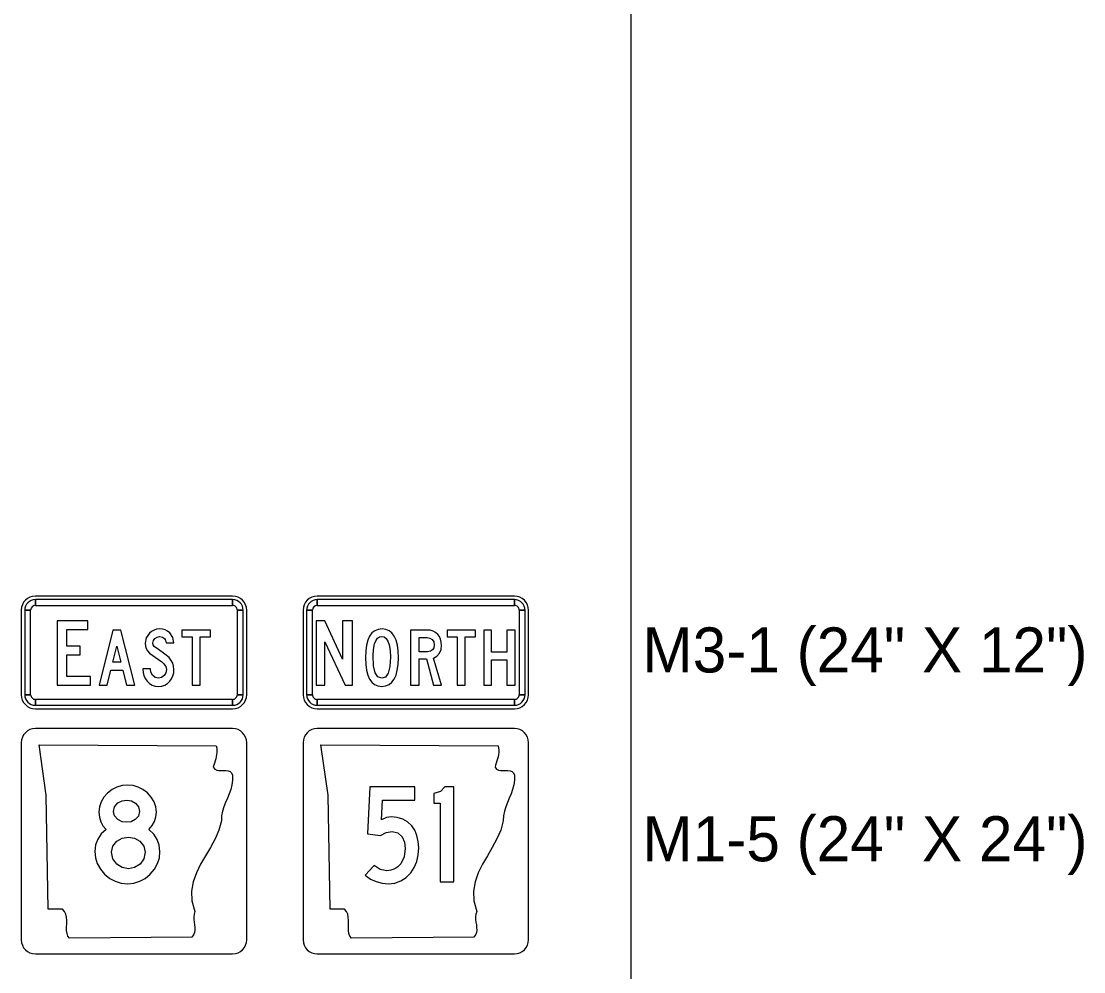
# Model space of a CAD drawing. Extents: x 1001568 to 1002149, y 1840825 to 1841423.
# Drawn here: x 1001915.24 to 1001924.67, y 1841286.31 to 1841294.75 of the extents above; entities that cross this region are included whole.
import ezdxf

# ---------------------------------------------------------------- set-up
doc = ezdxf.new("R2010")
doc.units = 0
for name, color, linetype in [('40', 7, 'Continuous'), ('R_No Plot', 7, 'Continuous'), ('SIGNS', 7, 'Continuous')]:
    doc.layers.add(name, color=color, linetype=linetype)

msp = doc.modelspace()

# ---------------------------------------------------------------- linework, layer by layer
at = {"layer": 'R_No Plot'}
msp.add_line((1001920.6501, 1841310.6666), (1001920.6501, 1841248.1274), dxfattribs=at)
at = {"layer": 'SIGNS'}
for p, q in [((1001917.1176, 1841289.6447), (1001915.3676, 1841289.6447)), ((1001919.6176, 1841289.6447), (1001917.8676, 1841289.6447)), ((1001915.3676, 1841289.5614), (1001915.3676, 1841289.6135)), ((1001917.1176, 1841289.6135), (1001917.1176, 1841289.5614)), ((1001917.8676, 1841289.5614), (1001917.8676, 1841289.6135)), ((1001919.6176, 1841289.6135), (1001919.6176, 1841289.5614)), ((1001915.2426, 1841289.5197), (1001915.2426, 1841288.7697)), ((1001915.2738, 1841289.5197), (1001915.3259, 1841289.5197)), ((1001917.1592, 1841289.5197), (1001917.2113, 1841289.5197)), ((1001917.2426, 1841288.7697), (1001917.2426, 1841289.5197)), ((1001917.7426, 1841289.5197), (1001917.7426, 1841288.7697)), ((1001917.7738, 1841289.5197), (1001917.8259, 1841289.5197)), ((1001919.6592, 1841289.5197), (1001919.7113, 1841289.5197)), ((1001919.7426, 1841288.7697), (1001919.7426, 1841289.5197)), ((1001915.3259, 1841288.7697), (1001915.2738, 1841288.7697)), ((1001915.3676, 1841288.676), (1001915.3676, 1841288.7281)), ((1001917.1176, 1841288.7281), (1001917.1176, 1841288.676)), ((1001917.2113, 1841288.7697), (1001917.1592, 1841288.7697)), ((1001917.8259, 1841288.7697), (1001917.7738, 1841288.7697)), ((1001917.8676, 1841288.676), (1001917.8676, 1841288.7281)), ((1001919.6176, 1841288.7281), (1001919.6176, 1841288.676)), ((1001919.7113, 1841288.7697), (1001919.6592, 1841288.7697)), ((1001915.3676, 1841288.6447), (1001917.1176, 1841288.6447)), ((1001917.8676, 1841288.6447), (1001919.6176, 1841288.6447)), ((1001917.1176, 1841288.4691), (1001915.3676, 1841288.4691)), ((1001919.6176, 1841288.4691), (1001917.8676, 1841288.4691)), ((1001915.2426, 1841288.3441), (1001915.2426, 1841286.5941)), ((1001917.2426, 1841286.5941), (1001917.2426, 1841288.3441)), ((1001917.7426, 1841288.3441), (1001917.7426, 1841286.5941)), ((1001919.7426, 1841286.5941), (1001919.7426, 1841288.3441)), ((1001915.2426, 1841286.5941), (1001915.2426, 1841286.5941)), ((1001917.7426, 1841286.5941), (1001917.7426, 1841286.5941)), ((1001915.3676, 1841286.4691), (1001917.1176, 1841286.4691)), ((1001917.8676, 1841286.4691), (1001919.6176, 1841286.4691))]:
    msp.add_line(p, q, dxfattribs=at)
for points in [[(1001917.1176, 1841289.6135), (1001915.3676, 1841289.6135), (1001915.3676, 1841289.5614), (1001917.1176, 1841289.5614), (1001917.1176, 1841289.6135), (1001917.1176, 1841289.6135)], [(1001919.6176, 1841289.6135), (1001917.8676, 1841289.6135), (1001917.8676, 1841289.5614), (1001919.6176, 1841289.5614), (1001919.6176, 1841289.6135), (1001919.6176, 1841289.6135)], [(1001915.2738, 1841289.5197), (1001915.2738, 1841288.7697), (1001915.3259, 1841288.7697), (1001915.3259, 1841289.5197), (1001915.2738, 1841289.5197), (1001915.2738, 1841289.5197)], [(1001917.2113, 1841288.7697), (1001917.2113, 1841289.5197), (1001917.1592, 1841289.5197), (1001917.1592, 1841288.7697), (1001917.2113, 1841288.7697), (1001917.2113, 1841288.7697)], [(1001917.7738, 1841289.5197), (1001917.7738, 1841288.7697), (1001917.8259, 1841288.7697), (1001917.8259, 1841289.5197), (1001917.7738, 1841289.5197), (1001917.7738, 1841289.5197)], [(1001919.7113, 1841288.7697), (1001919.7113, 1841289.5197), (1001919.6592, 1841289.5197), (1001919.6592, 1841288.7697), (1001919.7113, 1841288.7697), (1001919.7113, 1841288.7697)], [(1001915.8561, 1841288.9315), (1001915.6455, 1841288.9315), (1001915.6455, 1841289.1222), (1001915.765, 1841289.1222), (1001915.765, 1841289.2008), (1001915.6455, 1841289.2008), (1001915.6455, 1841289.3466), (1001915.8343, 1841289.3466), (1001915.8343, 1841289.4252), (1001915.5619, 1841289.4252), (1001915.5619, 1841288.8531), (1001915.8561, 1841288.8531)], [(1001916.3205, 1841289.0004), (1001916.3205, 1841288.9959), (1001916.3226, 1841288.966), (1001916.3296, 1841288.9384), (1001916.3417, 1841288.913), (1001916.3585, 1841288.8899), (1001916.3796, 1841288.8694), (1001916.4037, 1841288.855), (1001916.4301, 1841288.8464), (1001916.4594, 1841288.8435), (1001916.4886, 1841288.8462), (1001916.5152, 1841288.8547), (1001916.5388, 1841288.8687), (1001916.5598, 1841288.8885), (1001916.5762, 1841288.9112), (1001916.5879, 1841288.9363), (1001916.595, 1841288.9635), (1001916.5973, 1841288.9932), (1001916.5945, 1841289.0216), (1001916.5862, 1841289.0486), (1001916.5724, 1841289.0742), (1001916.5533, 1841289.0984), (1001916.5164, 1841289.1302), (1001916.4594, 1841289.1693), (1001916.4218, 1841289.1976), (1001916.4136, 1841289.2118), (1001916.4109, 1841289.2282), (1001916.4153, 1841289.2501), (1001916.4285, 1841289.2686), (1001916.4476, 1841289.281), (1001916.4703, 1841289.2853), (1001916.4946, 1841289.2812), (1001916.5123, 1841289.2695), (1001916.5219, 1841289.2529), (1001916.5292, 1841289.2283), (1001916.5973, 1841289.2283), (1001916.5862, 1841289.2784), (1001916.5602, 1841289.3177), (1001916.5412, 1841289.3331), (1001916.5197, 1841289.3442), (1001916.4952, 1841289.3508), (1001916.4683, 1841289.3531), (1001916.4434, 1841289.3506), (1001916.4203, 1841289.3435), (1001916.399, 1841289.3317), (1001916.3798, 1841289.3152), (1001916.3519, 1841289.274), (1001916.3427, 1841289.2262), (1001916.345, 1841289.2016), (1001916.352, 1841289.1791), (1001916.3637, 1841289.1582), (1001916.3802, 1841289.1393), (1001916.4599, 1841289.0823), (1001916.4895, 1841289.0598), (1001916.5078, 1841289.0431), (1001916.524, 1841289.0186), (1001916.5296, 1841288.9925), (1001916.5248, 1841288.9635), (1001916.5108, 1841288.9388), (1001916.4877, 1841288.9208), (1001916.4594, 1841288.9148), (1001916.4293, 1841288.9214), (1001916.4059, 1841288.9415), (1001916.3923, 1841288.9683), (1001916.3882, 1841289.0004)], [(1001917.8579, 1841288.8531), (1001917.9364, 1841288.8531), (1001917.9364, 1841289.2395), (1001918.117, 1841288.8531), (1001918.1809, 1841288.8531), (1001918.1809, 1841289.4252), (1001918.0935, 1841289.4252), (1001918.0935, 1841289.0839), (1001917.9364, 1841289.4252), (1001917.8579, 1841289.4252)], [(1001916.7578, 1841288.8531), (1001916.8289, 1841288.8531), (1001916.8289, 1841289.2818), (1001916.9204, 1841289.2818), (1001916.9204, 1841289.3434), (1001916.6682, 1841289.3434), (1001916.6682, 1841289.2818), (1001916.7578, 1841289.2818)], [(1001919.1098, 1841288.8531), (1001919.1809, 1841288.8531), (1001919.1809, 1841289.2818), (1001919.2724, 1841289.2818), (1001919.2724, 1841289.3434), (1001919.0202, 1841289.3434), (1001919.0202, 1841289.2818), (1001919.1098, 1841289.2818)], [(1001919.3472, 1841288.8531), (1001919.4145, 1841288.8531), (1001919.4145, 1841289.0781), (1001919.5491, 1841289.0781), (1001919.5491, 1841288.8531), (1001919.6241, 1841288.8531), (1001919.6241, 1841289.3434), (1001919.5491, 1841289.3434), (1001919.5491, 1841289.1468), (1001919.4145, 1841289.1468), (1001919.4145, 1841289.3434), (1001919.3472, 1841289.3434)], [(1001915.3676, 1841288.676), (1001917.1176, 1841288.676), (1001917.1176, 1841288.7281), (1001915.3676, 1841288.7281), (1001915.3676, 1841288.676), (1001915.3676, 1841288.676)], [(1001917.8676, 1841288.676), (1001919.6176, 1841288.676), (1001919.6176, 1841288.7281), (1001917.8676, 1841288.7281), (1001917.8676, 1841288.676), (1001917.8676, 1841288.676)], [(1001916.9725, 1841288.3147), (1001916.9772, 1841288.2956), (1001916.9788, 1841288.2762), (1001916.9782, 1841288.2571), (1001916.9758, 1841288.238), (1001916.9718, 1841288.2189), (1001916.9671, 1841288.2002), (1001916.9614, 1841288.1811), (1001916.9558, 1841288.1627), (1001916.9504, 1841288.1444), (1001916.9454, 1841288.126), (1001916.9594, 1841288.1099), (1001916.9768, 1841288.1007), (1001916.9965, 1841288.0967), (1001917.0179, 1841288.0963), (1001917.0393, 1841288.097), (1001917.06, 1841288.0974), (1001917.0791, 1841288.0952), (1001917.0958, 1841288.0889), (1001917.1088, 1841288.0768), (1001917.1168, 1841288.0566), (1001917.1175, 1841288.0111), (1001917.1118, 1841287.9685), (1001917.1012, 1841287.9281), (1001917.0868, 1841287.8896), (1001917.0711, 1841287.8514), (1001917.055, 1841287.8136), (1001917.04, 1841287.7751), (1001917.028, 1841287.7354), (1001917.0196, 1841287.6939), (1001917.0176, 1841287.6499), (1001916.9955, 1841287.5676), (1001916.9618, 1841287.4894), (1001916.921, 1841287.4138), (1001916.8769, 1841287.3389), (1001916.8338, 1841287.2644), (1001916.796, 1841287.1884), (1001916.768, 1841287.1098), (1001916.7536, 1841287.0272), (1001916.7569, 1841286.9399), (1001916.7827, 1841286.8463), (1001916.775, 1841286.8231), (1001916.7723, 1841286.7993), (1001916.773, 1841286.7754), (1001916.776, 1841286.7512), (1001916.7793, 1841286.7273), (1001916.782, 1841286.7038), (1001916.7827, 1841286.6807), (1001916.7793, 1841286.659), (1001916.771, 1841286.6377), (1001916.7556, 1841286.6179), (1001915.6719, 1841286.608), (1001915.6572, 1841286.6278), (1001915.6488, 1841286.6517), (1001915.6452, 1841286.6781), (1001915.6448, 1841286.7064), (1001915.6455, 1841286.7361), (1001915.6458, 1841286.7655), (1001915.6438, 1841286.7945), (1001915.6381, 1841286.8213), (1001915.6271, 1841286.8455), (1001915.6087, 1841286.8661), (1001915.4824, 1841286.8661), (1001915.4644, 1841287.8778), (1001915.4009, 1841288.3246), (1001916.9725, 1841288.3147), (1001916.9725, 1841288.3147)], [(1001919.4725, 1841288.3147), (1001919.4772, 1841288.2956), (1001919.4788, 1841288.2762), (1001919.4782, 1841288.2571), (1001919.4758, 1841288.238), (1001919.4718, 1841288.2189), (1001919.4671, 1841288.2002), (1001919.4614, 1841288.1811), (1001919.4558, 1841288.1627), (1001919.4504, 1841288.1444), (1001919.4454, 1841288.126), (1001919.4594, 1841288.1099), (1001919.4768, 1841288.1007), (1001919.4965, 1841288.0967), (1001919.5179, 1841288.0963), (1001919.5393, 1841288.097), (1001919.56, 1841288.0974), (1001919.5791, 1841288.0952), (1001919.5958, 1841288.0889), (1001919.6088, 1841288.0768), (1001919.6168, 1841288.0566), (1001919.6175, 1841288.0111), (1001919.6118, 1841287.9685), (1001919.6012, 1841287.9281), (1001919.5868, 1841287.8896), (1001919.5711, 1841287.8514), (1001919.555, 1841287.8136), (1001919.54, 1841287.7751), (1001919.528, 1841287.7354), (1001919.5196, 1841287.6939), (1001919.5176, 1841287.6499), (1001919.4955, 1841287.5676), (1001919.4618, 1841287.4894), (1001919.421, 1841287.4138), (1001919.3769, 1841287.3389), (1001919.3338, 1841287.2644), (1001919.296, 1841287.1884), (1001919.268, 1841287.1098), (1001919.2536, 1841287.0272), (1001919.2569, 1841286.9399), (1001919.2827, 1841286.8463), (1001919.275, 1841286.8231), (1001919.2723, 1841286.7993), (1001919.273, 1841286.7754), (1001919.276, 1841286.7512), (1001919.2793, 1841286.7273), (1001919.282, 1841286.7038), (1001919.2827, 1841286.6807), (1001919.2793, 1841286.659), (1001919.271, 1841286.6377), (1001919.2556, 1841286.6179), (1001918.1719, 1841286.608), (1001918.1572, 1841286.6278), (1001918.1488, 1841286.6517), (1001918.1452, 1841286.6781), (1001918.1448, 1841286.7064), (1001918.1455, 1841286.7361), (1001918.1458, 1841286.7655), (1001918.1438, 1841286.7945), (1001918.1381, 1841286.8213), (1001918.1271, 1841286.8455), (1001918.1087, 1841286.8661), (1001917.9824, 1841286.8661), (1001917.9644, 1841287.8778), (1001917.9009, 1841288.3246), (1001919.4725, 1841288.3147), (1001919.4725, 1841288.3147)], [(1001918.2929, 1841287.1669), (1001918.3405, 1841287.1339), (1001918.3905, 1841287.1106), (1001918.4427, 1841287.0968), (1001918.4974, 1841287.0922), (1001918.5567, 1841287.0982), (1001918.6098, 1841287.1163), (1001918.6567, 1841287.1468), (1001918.6977, 1841287.1898), (1001918.7284, 1841287.2373), (1001918.7503, 1841287.2899), (1001918.7635, 1841287.3474), (1001918.7681, 1841287.4104), (1001918.7642, 1841287.4678), (1001918.7526, 1841287.52), (1001918.7333, 1841287.5661), (1001918.7062, 1841287.6067), (1001918.6696, 1841287.6412), (1001918.6273, 1841287.6662), (1001918.5783, 1841287.6811), (1001918.5237, 1841287.6863), (1001918.4824, 1841287.6796), (1001918.4388, 1841287.6595), (1001918.448, 1841287.8349), (1001918.7351, 1841287.8349), (1001918.7351, 1841287.9504), (1001918.3343, 1841287.9504), (1001918.3139, 1841287.5345), (1001918.4303, 1841287.5195), (1001918.4793, 1841287.5455), (1001918.5322, 1841287.5543), (1001918.5842, 1841287.5424), (1001918.6222, 1841287.5076), (1001918.6418, 1841287.4616), (1001918.6485, 1841287.4046), (1001918.6384, 1841287.3299), (1001918.6084, 1841287.2687), (1001918.584, 1841287.2417), (1001918.5553, 1841287.2228), (1001918.5221, 1841287.2112), (1001918.4847, 1841287.2077), (1001918.4274, 1841287.2193), (1001918.3735, 1841287.2546)], [(1001918.9574, 1841287.1086), (1001919.0804, 1841287.1086), (1001919.0804, 1841287.9504), (1001918.999, 1841287.9504), (1001918.9607, 1841287.9091), (1001918.9023, 1841287.8936), (1001918.9023, 1841287.8055), (1001918.9574, 1841287.8055)]]:
    msp.add_lwpolyline(points, close=True, dxfattribs=at)
for points in [[(1001918.5878, 1841289.099), (1001918.5854, 1841289.1583), (1001918.5787, 1841289.21), (1001918.5674, 1841289.2536), (1001918.5516, 1841289.2895), (1001918.531, 1841289.3171), (1001918.5062, 1841289.3371), (1001918.4768, 1841289.349), (1001918.443, 1841289.3531), (1001918.4084, 1841289.349), (1001918.3785, 1841289.3371), (1001918.3533, 1841289.3171), (1001918.3327, 1841289.2895), (1001918.3166, 1841289.2536), (1001918.3052, 1841289.21), (1001918.2983, 1841289.1583), (1001918.2961, 1841289.099), (1001918.2982, 1841289.0389), (1001918.3049, 1841288.987), (1001918.3162, 1841288.943), (1001918.332, 1841288.9073), (1001918.3521, 1841288.8792), (1001918.3769, 1841288.8594), (1001918.4062, 1841288.8474), (1001918.44, 1841288.8435), (1001918.4745, 1841288.8474), (1001918.5046, 1841288.8594), (1001918.53, 1841288.8792), (1001918.5508, 1841288.9073), (1001918.567, 1841288.943), (1001918.5785, 1841288.987), (1001918.5854, 1841289.0389), (1001918.5878, 1841289.099)], [(1001915.9327, 1841288.8531), (1001916.0039, 1841288.8531), (1001916.0371, 1841288.9881), (1001916.1429, 1841288.9881), (1001916.1776, 1841288.8531), (1001916.2493, 1841288.8531), (1001916.1256, 1841289.3434), (1001916.0563, 1841289.3434), (1001915.9327, 1841288.8531)], [(1001918.5172, 1841289.1012), (1001918.5124, 1841289.0195), (1001918.498, 1841288.9613), (1001918.4741, 1841288.9264), (1001918.4407, 1841288.9148), (1001918.4068, 1841288.9271), (1001918.3826, 1841288.9644), (1001918.3682, 1841289.0264), (1001918.3633, 1841289.1136), (1001918.3664, 1841289.1714), (1001918.3757, 1841289.2195), (1001918.3868, 1841289.2489), (1001918.4014, 1841289.2702), (1001918.4192, 1841289.2829), (1001918.4407, 1841289.2872), (1001918.4618, 1841289.2826), (1001918.4797, 1841289.2686), (1001918.4942, 1841289.2453), (1001918.5055, 1841289.213), (1001918.5142, 1841289.1621), (1001918.5172, 1841289.1012)], [(1001918.6939, 1841288.8531), (1001918.7708, 1841288.8531), (1001918.7708, 1841289.0865), (1001918.8363, 1841289.0865), (1001918.9005, 1841288.8531), (1001918.9708, 1841288.8531), (1001918.8995, 1841289.0948), (1001918.9299, 1841289.1119), (1001918.9531, 1841289.139), (1001918.9662, 1841289.1703), (1001918.9708, 1841289.2061), (1001918.9687, 1841289.2356), (1001918.9623, 1841289.262), (1001918.952, 1841289.2851), (1001918.9376, 1841289.3051), (1001918.9185, 1841289.3218), (1001918.8959, 1841289.3338), (1001918.8699, 1841289.341), (1001918.8406, 1841289.3434), (1001918.6939, 1841289.3434), (1001918.6939, 1841288.8531)], [(1001918.7708, 1841289.1511), (1001918.7708, 1841289.2761), (1001918.8428, 1841289.2761), (1001918.868, 1841289.2718), (1001918.8881, 1841289.2591), (1001918.9011, 1841289.2392), (1001918.9054, 1841289.2133), (1001918.9015, 1841289.186), (1001918.8903, 1841289.1666), (1001918.8715, 1841289.1549), (1001918.8452, 1841289.1511), (1001918.7708, 1841289.1511)], [(1001916.0544, 1841289.0578), (1001916.089, 1841289.2002), (1001916.1256, 1841289.0578), (1001916.0544, 1841289.0578)], [(1001915.3676, 1841288.4691), (1001915.3676, 1841288.4691)], [(1001917.1176, 1841288.4691), (1001917.1176, 1841288.4691)], [(1001917.8676, 1841288.4691), (1001917.8676, 1841288.4691)], [(1001919.6176, 1841288.4691), (1001919.6176, 1841288.4691)], [(1001915.2426, 1841288.3441), (1001915.2426, 1841288.3441)], [(1001917.7426, 1841288.3441), (1001917.7426, 1841288.3441)], [(1001916.3755, 1841287.5744), (1001916.4039, 1841287.6077), (1001916.4242, 1841287.6443), (1001916.4366, 1841287.6843), (1001916.4408, 1841287.7276), (1001916.4356, 1841287.7754), (1001916.4209, 1841287.8199), (1001916.3961, 1841287.861), (1001916.3619, 1841287.8984), (1001916.3221, 1841287.9282), (1001916.2798, 1841287.9497), (1001916.2339, 1841287.9626), (1001916.1851, 1841287.967), (1001916.1364, 1841287.9623), (1001916.0907, 1841287.9492), (1001916.048, 1841287.9272), (1001916.0083, 1841287.8966), (1001915.9744, 1841287.8597), (1001915.9504, 1841287.8192), (1001915.9361, 1841287.775), (1001915.9314, 1841287.7276), (1001915.9352, 1841287.6822), (1001915.9474, 1841287.6418), (1001915.9675, 1841287.6056), (1001915.9959, 1841287.5744), (1001915.952, 1841287.5345), (1001915.9208, 1841287.4885), (1001915.902, 1841287.4367), (1001915.8958, 1841287.3789), (1001915.901, 1841287.3227), (1001915.9172, 1841287.2706), (1001915.9442, 1841287.2221), (1001915.9822, 1841287.1775), (1001916.0273, 1841287.1398), (1001916.0761, 1841287.1133), (1001916.1286, 1841287.0974), (1001916.1851, 1841287.0922), (1001916.2412, 1841287.0974), (1001916.2938, 1841287.1133), (1001916.3422, 1841287.1398), (1001916.3871, 1841287.1775), (1001916.4245, 1841287.2221), (1001916.4514, 1841287.2706), (1001916.4676, 1841287.3227), (1001916.4729, 1841287.3789), (1001916.4668, 1841287.4343), (1001916.4485, 1841287.4857), (1001916.418, 1841287.5324), (1001916.3755, 1841287.5744)], [(1001916.2919, 1841287.7315), (1001916.2824, 1841287.6917), (1001916.2537, 1841287.6605), (1001916.2179, 1841287.6427), (1001916.1779, 1841287.6368), (1001916.1364, 1841287.6427), (1001916.0998, 1841287.6614), (1001916.0704, 1841287.6933), (1001916.0609, 1841287.7341), (1001916.0704, 1841287.7754), (1001916.0998, 1841287.8086), (1001916.1364, 1841287.8282), (1001916.1779, 1841287.8349), (1001916.2197, 1841287.828), (1001916.2561, 1841287.8078), (1001916.2829, 1841287.7738), (1001916.2919, 1841287.7315)], [(1001916.3414, 1841287.3706), (1001916.3301, 1841287.3136), (1001916.2963, 1841287.2665), (1001916.2479, 1841287.2347), (1001916.1934, 1841287.2241), (1001916.1392, 1841287.2347), (1001916.0916, 1841287.2667), (1001916.0559, 1841287.3141), (1001916.0443, 1841287.3706), (1001916.0559, 1841287.4253), (1001916.0916, 1841287.4692), (1001916.138, 1841287.4957), (1001916.1934, 1841287.5047), (1001916.2483, 1841287.4957), (1001916.295, 1841287.4692), (1001916.3298, 1841287.4253), (1001916.3414, 1841287.3706)], [(1001915.3676, 1841286.4691), (1001915.3676, 1841286.4691)], [(1001917.1176, 1841286.4691), (1001917.1176, 1841286.4691)], [(1001917.8676, 1841286.4691), (1001917.8676, 1841286.4691)], [(1001919.6176, 1841286.4691), (1001919.6176, 1841286.4691)]]:
    msp.add_lwpolyline(points, dxfattribs=at)
for centre, radius, start, end in [((1001915.3676, 1841289.5197), 0.125, 90.00021, 179.99985), ((1001917.1176, 1841289.5197), 0.125, 0, 90.00021), ((1001917.8676, 1841289.5197), 0.125, 90.00021, 179.99985), ((1001919.6176, 1841289.5197), 0.125, 0, 90.00021), ((1001915.3676, 1841289.5197), 0.0937, 90.00021, 179.99985), ((1001915.3676, 1841289.5197), 0.0417, 90.00021, 179.99985), ((1001917.1176, 1841289.5197), 0.0937, 0, 90.00021), ((1001917.1176, 1841289.5197), 0.0417, 0, 90.00021), ((1001917.8676, 1841289.5197), 0.0937, 90.00021, 179.99985), ((1001917.8676, 1841289.5197), 0.0417, 90.00021, 179.99985), ((1001919.6176, 1841289.5197), 0.0937, 0, 90.00021), ((1001919.6176, 1841289.5197), 0.0417, 0, 90.00021), ((1001915.3676, 1841288.7697), 0.125, 179.99985, 270.00006), ((1001915.3676, 1841288.7697), 0.0937, 179.99985, 270.00006), ((1001915.3676, 1841288.7697), 0.0417, 179.99985, 270.00006), ((1001917.1176, 1841288.7697), 0.125, 270.00006, 0.00027), ((1001917.1176, 1841288.7697), 0.0937, 270.00006, 0.00027), ((1001917.1176, 1841288.7697), 0.0417, 270.00006, 0.00027), ((1001917.8676, 1841288.7697), 0.125, 179.99985, 270.00006), ((1001917.8676, 1841288.7697), 0.0937, 179.99985, 270.00006), ((1001917.8676, 1841288.7697), 0.0417, 179.99985, 270.00006), ((1001919.6176, 1841288.7697), 0.125, 270.00006, 0.00027), ((1001919.6176, 1841288.7697), 0.0937, 270.00006, 0.00027), ((1001919.6176, 1841288.7697), 0.0417, 270.00006, 0.00027), ((1001915.3676, 1841288.3441), 0.125, 90.00021, 179.99985), ((1001917.1176, 1841288.3441), 0.125, 0, 90), ((1001917.8676, 1841288.3441), 0.125, 90.00021, 179.99985), ((1001919.6176, 1841288.3441), 0.125, 0, 90), ((1001915.3676, 1841286.5941), 0.125, 180, 270), ((1001917.1176, 1841286.5941), 0.125, 270.00006, 0.00027), ((1001917.8676, 1841286.5941), 0.125, 180, 270), ((1001919.6176, 1841286.5941), 0.125, 270.00006, 0.00027)]:
    msp.add_arc(centre, radius, start, end, dxfattribs=at)

# ---------------------------------------------------------------- texts
at = {"layer": '40'}
for s, p in [('M3-1 (24" X 12")', (1001920.7531, 1841288.9666)), ('M1-5 (24" X 24")', (1001920.7531, 1841287.2911))]:
    msp.add_text(s, height=0.4, rotation=0, dxfattribs=at).set_placement(p)

doc.saveas('drawing.dxf')
